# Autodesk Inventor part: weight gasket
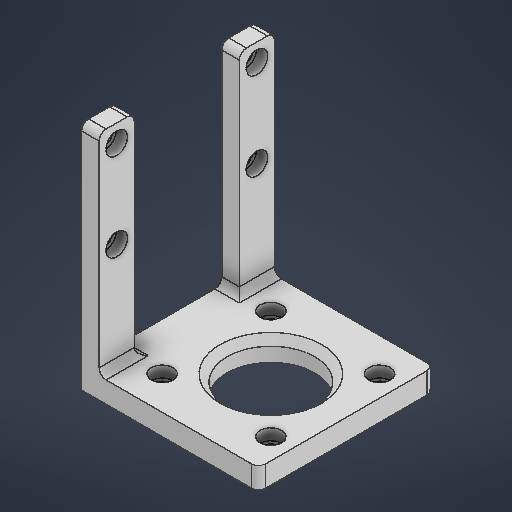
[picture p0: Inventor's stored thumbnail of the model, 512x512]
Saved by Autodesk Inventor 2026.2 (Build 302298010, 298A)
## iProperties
Created: 2026-05
Part Number: weight gasket
Material: 일반
Document SubType Name: Modeling
Designer: work
Density: 1 g/cm^3
Appearance: 기본값
Author: work
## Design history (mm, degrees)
sketch "스케치1"
  geometry: L1 (-12.5, 20)-(12.5, 20); L2 (12.5, 20)-(12.5, -20); L3 (12.5, -20)-(-12.5, -20); L4 (-12.5, -20)-(-12.5, 20); L5 (-12.5, 20)-(12.5, -20); L6 (12.5, 20)-(-12.5, -20); L7 (17.5, 25)-(-48.5, 25); L8 (-48.5, 25)-(-48.5, -25); L9 (-48.5, -25)-(17.5, -25); L10 (17.5, -25)-(17.5, 25); L11 (17.5, -15)-(-42.5, -15); L12 (-42.5, -15)-(-42.5, 15); L13 (-42.5, 15)-(17.5, 15); L14 (17.5, 15)-(17.5, -15); C1 r 2 at (12.5, 20); C2 r 2 at (-12.5, 20); C3 r 2 at (-12.5, -20); C4 r 2 at (12.5, -20); 4 further points
  constraints: 28 end point, 6 parallel, 4 centre point, 4 coincident, 4 midpoint, 3 horizontal, 3 perpendicular
  dimensions: "d0" = 25 distance of L2.end L3.end; "d1" = 40 distance of L1.end L2.end; "d2" = 4 diameter of C1; "d3" = 4 diameter of C2; "d4" = 4 diameter of C3; "d5" = 4 diameter of C4; "d6" = 5 distance between parallel lines of L9 L3; "d7" = 5 distance between parallel lines of L10 L2; "d8" = 5 distance between parallel lines of L7 L1; "d9" = 5 distance between parallel lines of L3 L11; "d10" = 6 distance between parallel lines of L8 L12; "d11" = 30 distance between parallel lines of L4 L12
extrude "돌출1" new body sketch "스케치1" distance "d12" = 6; taper "d13" = 0 deg
sketch "스케치2"
  geometry: L1 (0, 15)-(30, 15); L2 (0, -10)-(6, -10) reference; L3 (6, -10)-(51.5, -10); L4 (51.5, -10)-(51.5, 40); L5 (51.5, 40)-(6, 40); L6 (6, 40)-(6, -10); L7 (45.5, -0.5)-(14.5, -0.5); L8 (14.5, -0.5)-(14.5, 30.5); L9 (14.5, 30.5)-(45.5, 30.5); L10 (45.5, 30.5)-(45.5, -0.5); L11 (45.5, -0.5)-(14.5, 30.5); L12 (14.5, -0.5)-(45.5, 30.5); C1 r 2 at (45.5, -0.5); C2 r 2 at (45.5, 30.5); C3 r 2 at (14.5, 30.5); C4 r 2 at (14.5, -0.5); C5 r 12.5 at (30, 15); 1 further point
  constraints: 22 end point, 5 centre point, 5 coincident, 4 parallel, 3 horizontal, 2 midpoint, 2 perpendicular, 1 point on line
  dimensions: "d14" = 31 distance of L8.end L9.end; "d15" = 31 distance of L7.end L8.end; "d16" = 30 distance of L1.start L1.end; "d17" = 4 diameter of C1; "d18" = 4 diameter of C2; "d19" = 4 diameter of C3; "d20" = 4 diameter of C4; "d21" = 6 distance between parallel lines of L4 L10; "d22" = 25 diameter of C5
extrude "돌출2" join sketch "스케치2" distance "d23" = 6; taper "d24" = 0 deg
fillet "모깎기1" dims "d25" = 2
sketch "스케치3"
  geometry: C1 r 2 at (-37, 40.5) reference; C2 r 2 at (-6, 40.5) reference; C3 r 2 at (-6, 9.5) reference; C4 r 2 at (-37, 9.5) reference; 5 further points
  constraints: 4 coincident
hole "구멍1" sketch "스케치3" at (-37, 40.5), (-6, 40.5), (-6, 9.5), (-37, 9.5) diameter "d26" = 4; stored, may be unused: countersink angle "d30" = 90 deg, drill point angle "d32" = 118 deg; dims "d27" = 6, "d28" = 6.2, "d29" = 3.2, "d31" = 8
sketch "스케치4"
  geometry: C1 r 2 at (-20, 12.5) reference; C2 r 2 at (-20, -12.5) reference; C3 r 2 at (20, -12.5) reference; C4 r 2 at (20, 12.5) reference; 5 further points
  constraints: 4 coincident
hole "구멍2" sketch "스케치4" at (-20, 12.5), (-20, -12.5), (20, -12.5), (20, 12.5) diameter "d33" = 4; stored, may be unused: countersink angle "d37" = 90 deg, drill point angle "d39" = 118 deg; dims "d34" = 6, "d35" = 6.2, "d36" = 3.2, "d38" = 8
fillet "모깎기2" dims "d40" = 2
chamfer "모따기1" distance "d41" = 1; stored, may be unused: second distance "d42" = 2, angle "d43" = 45 deg
chamfer "모따기2" distance "d44" = 2; stored, may be unused: second distance "d45" = 2, angle "d46" = 45 deg
node "솔리드1"
feature "A9D066F2-1C7D-4E18-AEED-F7BC21143FA4" dims "d26" = 4, "d27" = 6, "d28" = 6.2, "d29" = 3.2, "d30" = 90 deg, "d31" = 8, "d32" = 118 deg
